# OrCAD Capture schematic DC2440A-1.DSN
size Custom
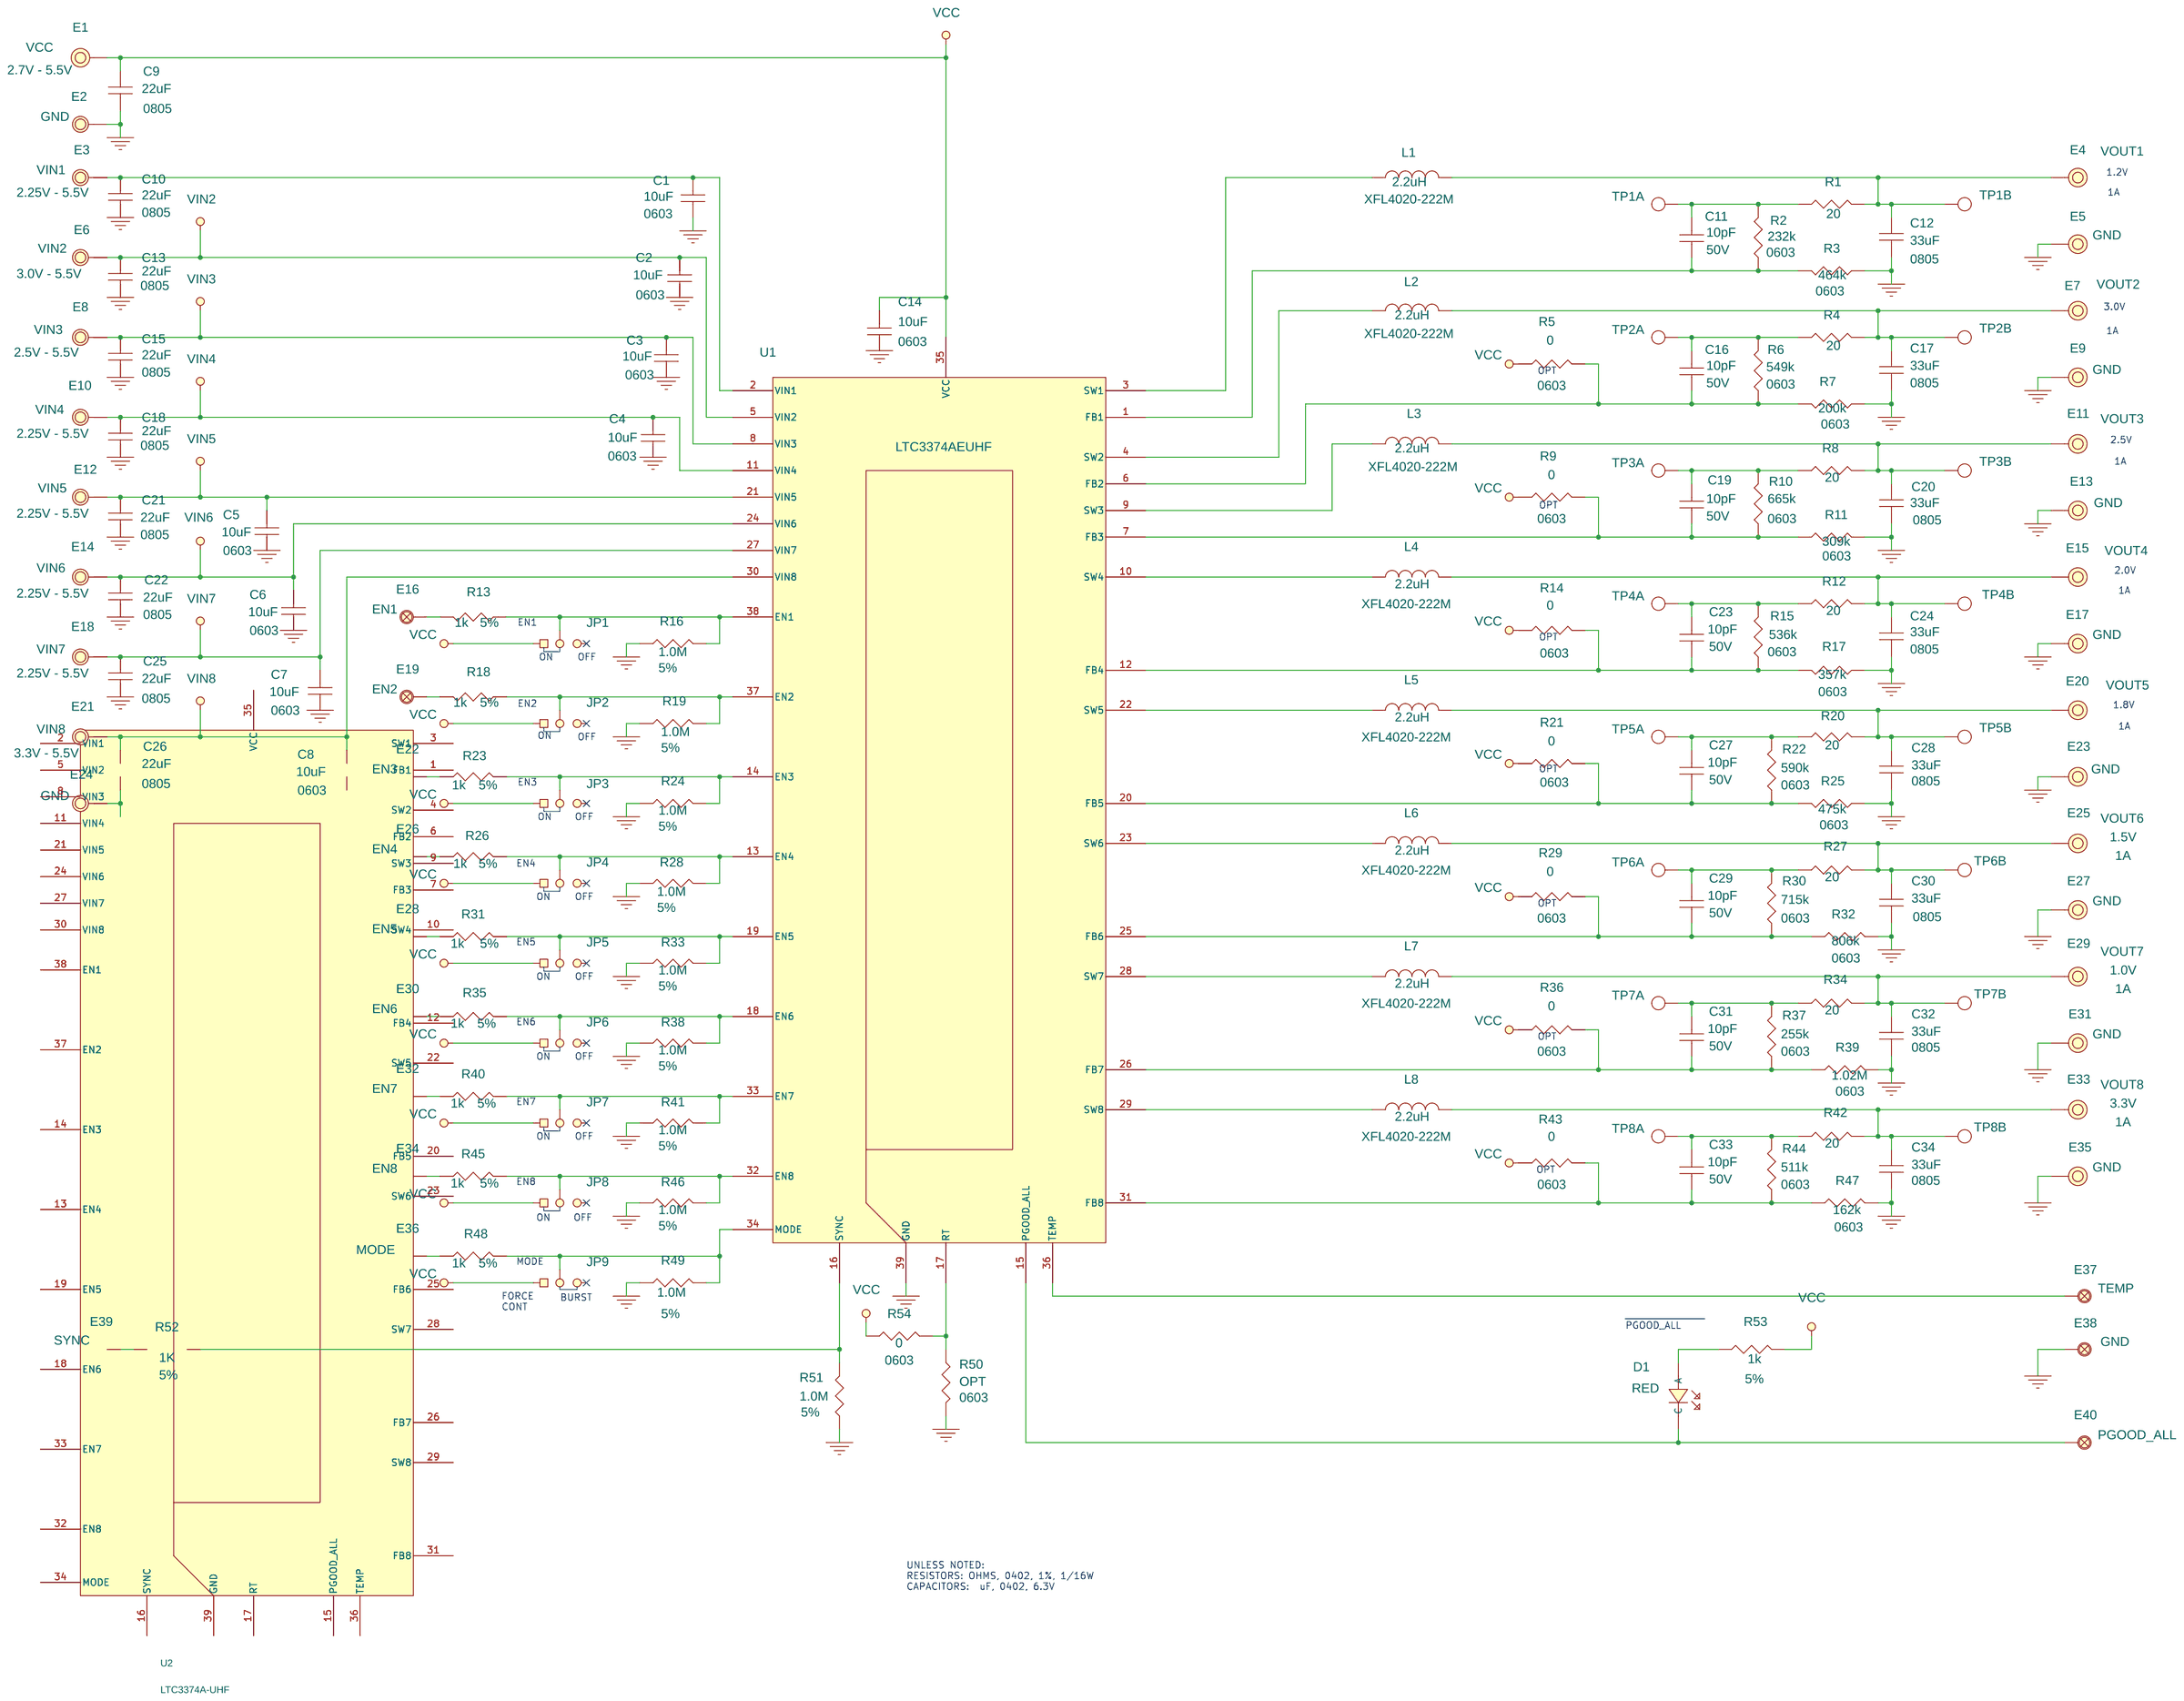
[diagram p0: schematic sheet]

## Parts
C1  10uF  [0603]
C2  10uF  [0603]
C3  10uF  [0603]
C4  10uF  [0603]
C5  10uF  [0603]
C6  10uF  [0603]
C7  10uF  [0603]
C8  10uF  [0603]
C9  22uF  [0805]
C10  22uF  [0805]
C11  10pF  [0402-SMALL]
C12  33uF  [0805]
C13  22uF  [0805]
C14  10uF  [0603]
C15  22uF  [0805]
C16  10pF  [0402-SMALL]
C17  33uF  [0805]
C18  22uF  [0805]
C19  10pF  [0402-SMALL]
C20  33uF  [0805]
C21  22uF  [0805]
C22  22uF  [0805]
C23  10pF  [0402-SMALL]
C24  33uF  [0805]
C25  22uF  [0805]
C26  22uF  [0805]
C27  10pF  [0402-SMALL]
C28  33uF  [0805]
C29  10pF  [0402-SMALL]
C30  33uF  [0805]
C31  10pF  [0402-SMALL]
C32  33uF  [0805]
C33  10pF  [0402-SMALL]
C34  33uF  [0805]
D1  RED  [LNJ208R8ARA-RED-LED]
E1  VCC  [MILL-MAX-2501-2]
E2  GND  [MILL-MAX-2501-2]
E3  VIN1  [MILL-MAX-2501-2]
E4  VOUT1  [MILL-MAX-2501-2]
E5  GND  [MILL-MAX-2501-2]
E6  VIN2  [MILL-MAX-2501-2]
E7  VOUT2  [MILL-MAX-2501-2]
E8  VIN3  [MILL-MAX-2501-2]
E9  GND  [MILL-MAX-2501-2]
E10  VIN4  [MILL-MAX-2501-2]
E11  VOUT3  [MILL-MAX-2501-2]
E12  VIN5  [MILL-MAX-2501-2]
E13  GND  [MILL-MAX-2501-2]
E14  VIN6  [MILL-MAX-2501-2]
E15  VOUT4  [MILL-MAX-2501-2]
E16  EN1  [MILL-MAX-2308]
E17  GND  [MILL-MAX-2501-2]
E18  VIN7  [MILL-MAX-2501-2]
E19  EN2  [MILL-MAX-2308]
E20  VOUT5  [MILL-MAX-2501-2]
E21  VIN8  [MILL-MAX-2501-2]
E22  EN3  [MILL-MAX-2308]
E23  GND  [MILL-MAX-2501-2]
E24  GND  [MILL-MAX-2501-2]
E25  VOUT6  [MILL-MAX-2501-2]
E26  EN4  [MILL-MAX-2308]
E27  GND  [MILL-MAX-2501-2]
E28  EN5  [MILL-MAX-2308]
E29  VOUT7  [MILL-MAX-2501-2]
E30  EN6  [MILL-MAX-2308]
E31  GND  [MILL-MAX-2501-2]
E32  EN7  [MILL-MAX-2308]
E33  VOUT8  [MILL-MAX-2501-2]
E34  EN8  [MILL-MAX-2308]
E35  GND  [MILL-MAX-2501-2]
E36  MODE  [MILL-MAX-2308]
E37  TEMP  [MILL-MAX-2308]
E38  GND  [MILL-MAX-2308]
E39  SYNC  [MILL-MAX-2308]
E40  PGOOD_ALL  [MILL-MAX-2308]
JP1  3 PINS, 2mm  [2MMJUMP3]
JP2  3 PINS, 2mm  [2MMJUMP3]
JP3  3 PINS, 2mm  [2MMJUMP3]
JP4  3 PINS, 2mm  [2MMJUMP3]
JP5  3 PINS, 2mm  [2MMJUMP3]
JP6  3 PINS, 2mm  [2MMJUMP3]
JP7  3 PINS, 2mm  [2MMJUMP3]
JP8  3 PINS, 2mm  [2MMJUMP3]
JP9  3 PINS, 2mm  [2MMJUMP3]
L1  2.2uH  [IND-XFL4020]
L2  2.2uH  [IND-XFL4020]
L3  2.2uH  [IND-XFL4020]
L4  2.2uH  [IND-XFL4020]
L5  2.2uH  [IND-XFL4020]
L6  2.2uH  [IND-XFL4020]
L7  2.2uH  [IND-XFL4020]
L8  2.2uH  [IND-XFL4020]
R1  20  [0402-SMALL]
R2  232k  [CC0603L]
R3  464k  [CC0603L]
R4  20  [0402-SMALL]
R5  0  [CC0603L]
R6  549k  [CC0603L]
R7  200k  [CC0603L]
R8  20  [0402-SMALL]
R9  0  [CC0603L]
R10  665k  [CC0603L]
R11  309k  [CC0603L]
R12  20  [0402-SMALL]
R13  1k  [0402-SMALL]
R14  0  [CC0603L]
R15  536k  [CC0603L]
R16  1.0M  [0402-SMALL]
R17  357k  [CC0603L]
R18  1k  [0402-SMALL]
R19  1.0M  [0402-SMALL]
R20  20  [0402-SMALL]
R21  0  [CC0603L]
R22  590k  [CC0603L]
R23  1k  [0402-SMALL]
R24  1.0M  [0402-SMALL]
R25  475k  [CC0603L]
R26  1k  [0402-SMALL]
R27  20  [0402-SMALL]
R28  1.0M  [0402-SMALL]
R29  0  [CC0603L]
R30  715k  [CC0603L]
R31  1k  [0402-SMALL]
R32  806k  [CC0603L]
R33  1.0M  [0402-SMALL]
R34  20  [0402-SMALL]
R35  1k  [0402-SMALL]
R36  0  [CC0603L]
R37  255k  [CC0603L]
R38  1.0M  [0402-SMALL]
R39  1.02M  [CC0603L]
R40  1k  [0402-SMALL]
R41  1.0M  [0402-SMALL]
R42  20  [0402-SMALL]
R43  0  [CC0603L]
R44  511k  [CC0603L]
R45  1k  [0402-SMALL]
R46  1.0M  [0402-SMALL]
R47  162k  [CC0603L]
R48  1k  [0402-SMALL]
R49  1.0M  [0402-SMALL]
R50  OPT  [CC0603L]
R51  1.0M  [0402-SMALL]
R52  1K  [0402-SMALL]
R53  1k  [0402-SMALL]
R54  0  [CC0603L]
TP1A  SMT  [PAD70-70]
TP1B  SMT  [PAD70-70]
TP2A  SMT  [PAD70-70]
TP2B  SMT  [PAD70-70]
TP3A  SMT  [PAD70-70]
TP3B  SMT  [PAD70-70]
TP4A  SMT  [PAD70-70]
TP4B  SMT  [PAD70-70]
TP5A  SMT  [PAD70-70]
TP5B  SMT  [PAD70-70]
TP6A  SMT  [PAD70-70]
TP6B  SMT  [PAD70-70]
TP7A  SMT  [PAD70-70]
TP7B  SMT  [PAD70-70]
TP8A  SMT  [PAD70-70]
TP8B  SMT  [PAD70-70]
U1  LTC3374  [UHF_38]
U2  LTC3374A-UHF  [LTC-UHF-38-1701]

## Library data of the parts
C1 C9 C10 C13 C15 C18 C21 C22 C25 C26 = C1608X5R0J475M: 1st Part Field: 6.3V; 3rd Part Field: CHIP, X5R; 4th Part Field: T. yuden; 5th Part Field: JMK212BJ226MG; 7th Part Field: CAP, X5R; Tolerance: 20%
C2 C3 = C1608X5R0J475M: 1st Part Field: 6.3V; 3rd Part Field: CHIP, X5R; 4th Part Field: MUR; 5th Part Field: GRM188R60J106ME47; 7th Part Field: CAP, X5R; Tolerance: 20%
C4-C8 = C1608X5R0J475M: 1st Part Field: 10V; 3rd Part Field: CHIP, X5R; 4th Part Field: MUR; 5th Part Field: GRM188R60J106ME47; 7th Part Field: CAP, X5R; Tolerance: 20%
C11 C16 C19 C23 C27 C29 C31 C33 = C2012X5R0J156M: 1st Part Field: 50V; 2nd Part Field: 0402; 3rd Part Field: CHIP; 4th Part Field: AVX; 5th Part Field: 04025A100KAT; 7th Part Field: CAP, COG; Part Number: AVX, 04015A100KAT
C12 = C1608X5R0J475M: 1st Part Field: 6.3V; 3rd Part Field: CHIP; 4th Part Field: TDK; 5th Part Field: GRM155R60J225ME15; 7th Part Field: CAP, X5R; Part Number: C2012X5R0J336M; Tolerance: 20%
C14 = C1608X5R0J475M: 1st Part Field: 6.3V; 3rd Part Field: CHIP,; 4th Part Field: T. Yuden; 5th Part Field: JMK212BJ226MG; 7th Part Field: CAP, X5R; Tolerance: 20%
C17 C20 C24 = C1608X5R0J475M: 1st Part Field: 6.3V; 3rd Part Field: CHIP; 4th Part Field: TDK; 5th Part Field: C2012X5R0J336M; 7th Part Field: CAP, X5R; Part Number: C2012X5R0J336M; Tolerance: 20%; Voltage: 6.3V
C28 C30 = C2012X5R0J156M: 1st Part Field: 6.3V; 3rd Part Field: CHIP, X5R; 4th Part Field: TDK; 5th Part Field: C2012X5R0J336M; 7th Part Field: CAP,; Part Number: C2012X5R0J336M; Tolerance: 20%; Voltage: 6.3V
C32 C34 = C2012X5R0J156M: 1st Part Field: 6.3V; 3rd Part Field: CHIP, X5R; 4th Part Field: TDK; 5th Part Field: C2012X5R0J336M; 7th Part Field: CAP,; Part Number: TDK, C2012X5R0J336M; Tolerance: 20%; Voltage: 6.3V
D1 = LNJ208R8ARA_(RED-LED)_0
E1 = E_3: TURRET; 3V to 4.2V: 2.7V - 5.5V; IBAT: 5mA
E2 E24 = MillMax-2501-2: 4th Part Field: MILL-MAX; 9th Part Field: t
E3 E10 E12 E14 E18 = MillMax-2501-2: 10th Part Field: VBUS; 4th Part Field: MILL-MAX; 9th Part Field: 2.25V - 5.5V
E4 E5 E7 E9 E11 E13 E15 E17 E20 E23 E27 E31 E35 = E_3: TURRET
E6 = MillMax-2501-2: 10th Part Field: VBUS; 4th Part Field: MILL-MAX; 9th Part Field: 3.0V - 5.5V
E8 = MillMax-2501-2: 10th Part Field: VBUS; 4th Part Field: MILL-MAX; 9th Part Field: 2.5V - 5.5V
E16 = TP_KEY_1502-2_0: 4th Part Field: MILL-MAX; 5th Part Field: 2308-2; 7th Part Field: TURRET, SIGNAL; Part Number: MILL-MAX 2308-2
E19 E22 E26 E28 E30 E32 E34 E36-E40 = TP_KEY_1502-2_0: 4th Part Field: MILL-MAX; 5th Part Field: 2308-2; 7th Part Field: TURRET, SIGNAL; 9th Part Field: EN1; Part Number: MILL-MAX 2308-2
E21 = MillMax-2501-2: 10th Part Field: VBUS; 4th Part Field: MILL-MAX; 9th Part Field: 3.3V - 5.5V
E25 = E_3: TURRET; 3V to 4.2V: 1.5V; IOUT: 1A
E29 = E_3: TURRET; 3V to 4.2V: 1.0V; IOUT: 1A
E33 = E_3: TURRET; 3V to 4.2V: 3.3V; IOUT: 1A
JP1-JP9 = JP3X1_079_NO_1: 4TH PART FIELD: SAMTEC; 5TH PART FIELD: TMM-103-02-L-S; 7TH PART FIELD: HEADER; Part Number: TMM-103-02-L-S
L1 L2 = CR75-100MC: 4th Part Field: CoilCraft; 5th Part Field: XFL4020-222M; Part Number: LPS4018-2R2
L3-L8 = CR75-100MC: 4th Part Field: TOKO; 5th Part Field: XFL4020-222M; Part Number: 1072AS-3R3M
R1 R4 R8 R12 R20 = CR16-103JM_0: 2nd Part Field: 0402; 3rd Part Field: CHIP; 4th Part Field: VISHAY; 5th Part Field: CRCW040220R0F; 7th Part Field: RES; Part Number: VISHAY CRCW0402 20 1%; Tolerance: 1%
R2 R6 R10 R15 = CR16-103JM_0: 2nd Part Field: 0603; 3rd Part Field: CHIP; 4th Part Field: VISHAY; 5th Part Field: CRCW04021024F; 7th Part Field: RES; Part Number: VISHAY CRCW0402 1.02M 1%; Tolerance: 1%
R3 R7 R11 R17 = CR16-103JM_0: 2nd Part Field: 0603; 3rd Part Field: CHIP; 4th Part Field: VISHAY; 5th Part Field: CRCW04023243F; 7th Part Field: RES; Part Number: VISHAY CRCW0402 324k 1%; Tolerance: 1%
R5 R9 R14 R21 R29 R36 R43 R54 = CR16-103JM_0: 1st Part Field: 1/16W; 2nd Part Field: 0603; 3rd Part Field: CHIP; 4th Part Field: VISHAY; 5th Part Field: CRCW040220R0JNED; 7th Part Field: RES,; Critical: T; Layer: B; MPN: CRCW040220R0JNED; Manufacturer: VISHAY; Part Number: VISHAY CRCW0402 20 5%; Populate: T; Size: 0402; Tempco: 200PPM; Tolerance: 5%; Voltage: 30V; Wattage: 1/16W
R13 R16 R18 R19 R23 R24 R26 R28 R31 R33 R35 R38 R40 R41 R45 R46 R48 R49 R51 R52 = CR16-103JM_0: 2nd Part Field: 0402; 3rd Part Field: CHIP; 4th Part Field: VISHAY; 5th Part Field: CRCW04021003F; 7th Part Field: RES; Part Number: VISHAY CRCW0402 100K 1%; Tolerance: 5%
R22 R25 R30 R37 R44 = CR16-103JM_0: 2nd Part Field: 0603; 3rd Part Field: CHIP; 4th Part Field: VISHAY; 5th Part Field: CRCW04021004F; 7th Part Field: RES,; Part Number: VISHAY CRCW0402 1M 1%; Tolerance: 1%
R27 R34 R42 = CR16-103JM_0: 1st Part Field: 1/16W; 2nd Part Field: 0402; 3rd Part Field: CHIP; 4th Part Field: VISHAY; 5th Part Field: CRCW040220R0JNED; 7th Part Field: RES,; Critical: T; Layer: B; MPN: CRCW040220R0JNED; Manufacturer: VISHAY; Part Number: VISHAY CRCW0402 20 5%; Populate: T; Size: 0402; Tempco: 200PPM; Tolerance: 5%; Voltage: 30V; Wattage: 1/16W
R32 R39 R47 = CR16-103JM_0: 1st Part Field: 1/16W; 2nd Part Field: 0603; 3rd Part Field: CHIP; 4th Part Field: VISHAY; 5th Part Field: CRCW0402105KFKED; 7th Part Field: RES,; Critica: T; Layer: T; MPN: CRCW0402105KFKED; Manufacturer: VISHAY; Part Number: VISHAY CRCW0402 105K 1%; Populate: T; Size: 0402; Tempco: 200PPM; Tolerance: 1%; Voltage: 30V; Wattage: 1/16W
R50 = CR16-103JM_0: 2nd Part Field: 0603; 3rd Part Field: CHIP; 4th Part Field: VISHAY; 5th Part Field: CRCW04021003F; 7th Part Field: RES; Part Number: VISHAY CRCW0402 100K 1%; Tolerance: 1%
R53 = CR16-103JM_0: 2nd Part Field: 0402; 3rd Part Field: CHIP; 4th Part Field: VISHAY; 5th Part Field: CRCW04021004F; 7th Part Field: RES; Part Number: VISHAY CRCW0402 1.02M 1%; Tolerance: 5%
TP1A TP1B TP2A TP2B TP3A TP3B TP4A TP4B TP5A TP5B TP6A TP6B TP7A TP7B TP8A TP8B = TP_KEY_1502-2: 7th Part Field: TEST POINT; 9th Part Field: INJ; Layer: B
U1 = UFF_PKG_44L_QFN_41: 1st Part Field: 6V; 2nd Part Field: 4x4 QFN; 3rd Part Field: USB PWR MGR; 4th Part Field: LINEAR; 5th Part Field: LTC3374AEUHF; 7th Part Field: IC
U2 = LTC3374A-UHF

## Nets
GND: C1.1 C2.1 C3.1 C4.1 C5.1 C6.1 C7.1 C8.1 C9.2 C10.2 C12.2 C13.2 C14.1 C15.2 C17.2 C18.2 C20.2 C21.2 C22.2 C24.2 C25.2 C26.2 C28.2 C30.2 C32.2 C34.2 E2.1 E5.1(A) E9.1(A) E13.1(A) E17.1(A) E23.1(A) E24.1 E27.1(A) E31.1(A) E35.1(A) E38.1 R3.1 R7.1 R11.2 R16.2 R17.1 R19.2 R24.2 R25.2 R28.2 R32.1 R33.2 R38.2 R39.1 R41.2 R46.2 R47.1 R49.2 R50.1 R51.2 U1.39(GND)
VCC: C9.1 C14.2 E1.1(A) JP1.1 JP2.1 JP3.1 JP4.1 JP5.1 JP6.1 JP7.1 JP8.1 JP9.1 R53.2 R54.2 U1.35(VCC)
VIN2: C2.2 C13.1 E6.1 R5.2 U1.5(VIN2)
VIN3: C3.2 C15.1 E8.1 R9.2 U1.8(VIN3)
VIN4: C4.2 C18.1 E10.1 R14.2 U1.11(VIN4)
VIN5: C5.2 C21.1 E12.1 R21.2 U1.21(VIN5)
VIN6: C6.2 C22.1 E14.1 R29.2 U1.24(VIN6)
VIN7: C7.2 C25.1 E18.1 R36.2 U1.27(VIN7)
VIN8: C8.2 C26.1 E21.1 R43.2 U1.30(VIN8)
N16596435: JP1.2 R13.2 R16.1 U1.38(EN1)
N16596735: JP2.2 R18.2 R19.1 U1.37(EN2)
N16788362: C24.1 E15.1(A) L4.2 R12.2 TP4B.1
N16789921: D1.1(C) E40.1 U1.15(PGOOD_ALL)
N16831805: C11.1 R2.1 R3.2 U1.1(FB1)
N16832335: C17.1 E7.1(A) L2.2 R4.2 TP2B.1
N16835243: JP3.2 R23.1 R24.1 U1.14(EN3)
N16835502: JP4.2 R26.1 R28.1 U1.13(EN4)
N16835602: JP5.2 R31.1 R33.1 U1.19(EN5)
N16839888: C1.2 C10.1 E3.1 U1.2(VIN1)
N16842547: C30.1 E25.1(A) L6.2 R27.1 TP6B.1
N16848723: C12.1 E4.1(A) L1.2 R1.2 TP1B.1
N16849848: C16.2 R4.1 R6.2 TP2A.1
N16849887: C16.1 R5.1 R6.1 R7.2 U1.6(FB2)
N16851798: C19.1 R9.1 R10.1 R11.1 U1.7(FB3)
N16851879: C19.2 R8.1 R10.2 TP3A.1
N16852077: C20.1 E11.1(A) L3.2 R8.2 TP3B.1
N16857818: C28.1 E20.1(A) L5.2 R20.2 TP5B.1
N16874766: C11.2 R1.1 R2.2 TP1A.1
N16875915: C23.1 R14.1 R15.1 R17.2 U1.12(FB4)
N16875949: C23.2 R12.1 R15.2 TP4A.1
N16877319: C27.2 R20.1 R22.1 TP5A.1
N16877332: C27.1 R21.1 R22.2 R25.1 U1.20(FB5)
N16889576: L1.1 U1.3(SW1)
N16890519: L2.1 U1.4(SW2)
N17033039: C29.2 R27.2 R30.1 TP6A.1
N17094829: JP6.2 R35.1 R38.1 U1.18(EN6)
N17094986: JP7.2 R40.1 R41.1 U1.33(EN7)
N17095145: JP8.2 R45.1 R46.1 U1.32(EN8)
N17103127: E39.1 R52.2
N17103260: R51.1 R52.1 U1.16(SYNC)
N17116088: L3.1 U1.9(SW3)
N17116263: L4.1 U1.10(SW4)
N17117212: L5.1 U1.22(SW5)
N17121341: C29.1 R29.1 R30.2 R32.2 U1.25(FB6)
N17121732: L6.1 U1.23(SW6)
N17124316: C31.1 R36.1 R37.2 R39.2 U1.26(FB7)
N17124331: C31.2 R34.2 R37.1 TP7A.1
N17124363: C32.1 E29.1(A) L7.2 R34.1 TP7B.1
N17125135: C34.1 E33.1(A) L8.2 R42.1 TP8B.1
N17125163: C33.1 R43.1 R44.2 R47.2 U1.31(FB8)
N17125209: C33.2 R42.2 R44.1 TP8A.1
N17125510: L7.1 U1.28(SW7)
N17125643: L8.1 U1.29(SW8)
N17129900: R50.2 R54.1 U1.17(RT)
N17135355: E37.1 U1.36(TEMP)
N17224805: E16.1 R13.1
N17225746: E19.1 R18.1
N17225747: E22.1 R23.2
N17225748: E26.1 R26.2
N17225749: E28.1 R31.2
N17225750: E30.1 R35.2
N17225751: E32.1 R40.2
N17225752: E34.1 R45.2
N17240389: D1.2(A) R53.1
N17247089: JP9.2 R48.1 R49.1 U1.34(MODE)
N17247158: E36.1 R48.2

Not connected (* = marked no-connect by the designer): JP1 3*; JP2 3*; JP3 3*; JP4 3*; JP5 3*; JP6 3*; JP7 3*; JP8 3*; JP9 3*; U2 1(FB1) 2(VIN1) 3(SW1) 4(SW2) 5(VIN2) 6(FB2) 7(FB3) 8(VIN3) 9(SW3) 10(SW4) 11(VIN4) 12(FB4) 13(EN4) 14(EN3) 15(PGOOD_ALL) 16(SYNC) 17(RT) 18(EN6) 19(EN5) 20(FB5) 21(VIN5) 22(SW5) 23(SW6) 24(VIN6) 25(FB6) 26(FB7) 27(VIN7) 28(SW7) 29(SW8) 30(VIN8) 31(FB8) 32(EN8) 33(EN7) 34(MODE) 35(VCC) 36(TEMP) 37(EN2) 38(EN1) 39(GND)

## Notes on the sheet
- 1.2V
- 1A
- 3.0V
- 1A
- OPT
- 2.5V
- 1A
- OPT
- 2.0V
- 1A
- EN1
- OPT
- ON
- OFF
- EN2
- 1.8V
- ON
- OFF
- 1A
- EN3
- OPT
- ON
- OFF
- EN4
- ON
- OFF
- OPT
- EN5
- ON
- OFF
- EN6
- OPT
- ON
- OFF
- EN7
- ON
- OFF
- OPT
- EN8
- ON
- OFF
- MODE
- FORCE
  CONT
- BURST
- PGOOD_ALL
- UNLESS NOTED:
  RESISTORS: OHMS, 0402, 1%, 1/16W
  CAPACITORS:  uF, 0402, 6.3V
